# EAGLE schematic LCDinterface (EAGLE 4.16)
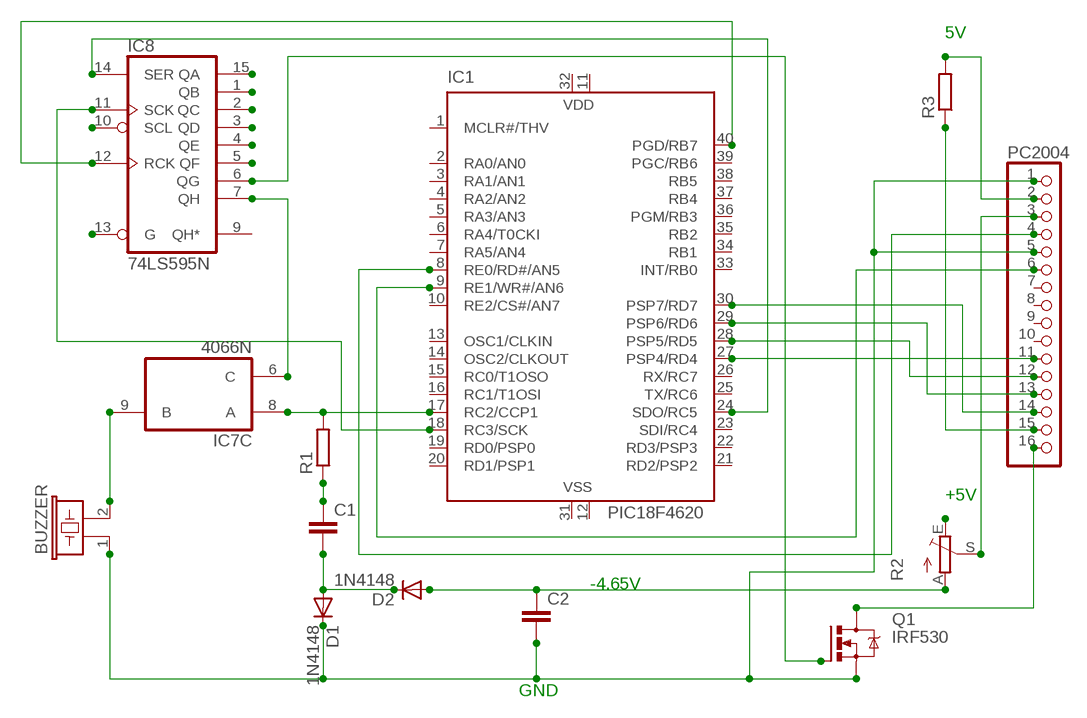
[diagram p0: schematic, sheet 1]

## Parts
BUZZER  B/C11L  [B/C11L]
C1  C-EU050-025X075  [C050-025X075]
C2  C-EU050-025X075  [C050-025X075]
D1  1N4148  [DO35-10]
D2  1N4148  [DO35-10]
IC1  PIC18F4620  PIC16F874P  [DIL40]
IC7  4066N  [DIL14]
IC8  74LS595N  [DIL16]
PC2004  PINHD-1X16  [1X16]
Q1  IRF530  [TO220BV]
R1  R-EU_0309/12  [0309/12]
R2  TRIM_EU-ECP10P  [ECP10P]
R3  R-EU_0309/12  [0309/12]

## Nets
N$1: IC7.6(C:C) IC8.7(QH)
N$2: IC1.17(RC2/CCP1) IC7.8(C:A) R1.2
N$3: BUZZER.2 IC7.9(C:B)
N$4: C1.1 R1.1
N$6: PC2004.15 R3.1
N$7: C1.2 D1.A D2.C
N$8: PC2004.2 R3.2
N$9: IC1.18(RC3/SCK) IC8.11(SCK)
N$10: PC2004.16 Q1.D
N$12: C2.1 D2.A R2.A
N$13: R2.E
N$14: IC8.6(QG) Q1.G
N$15: PC2004.3 R2.S
N$16: IC1.40(PGD/RB7) IC8.12(RCK)
N$19: IC1.24(SDO/RC5) IC8.14(SER)
N$20: IC1.30(PSP7/RD7) PC2004.14
N$21: IC1.29(PSP6/RD6) PC2004.13
N$22: IC1.28(PSP5/RD5) PC2004.12
N$23: IC1.27(PSP4/RD4) PC2004.11
N$28: IC1.8(RE0/RD#/AN5) PC2004.4
N$29: BUZZER.1 C2.2 D1.C PC2004.1 PC2004.5 Q1.S
N$30: IC1.9(RE1/WR#/AN6) PC2004.6
N$32: IC8.15(QA)
N$33: IC8.1(QB)
N$34: IC8.2(QC)
N$35: IC8.3(QD)
N$36: IC8.4(QE)
N$37: IC8.5(QF)
N$38: IC8.13(G)
N$39: IC8.10(SCL)
Unconnected: IC1.1(MCLR#/THV) IC1.2(RA0/AN0) IC1.3(RA1/AN1) IC1.4(RA2/AN2) IC1.5(RA3/AN3) IC1.6(RA4/T0CKI) IC1.7(RA5/AN4) IC1.10(RE2/CS#/AN7) IC1.13(OSC1/CLKIN) IC1.14(OSC2/CLKOUT) IC1.15(RC0/T1OSO) IC1.16(RC1/T1OSI) IC1.19(RD0/PSP0) IC1.20(RD1/PSP1) IC1.21(RD2/PSP2) IC1.22(RD3/PSP3) IC1.23(SDI/RC4) IC1.25(TX/RC6) IC1.26(RX/RC7) IC1.33(INT/RB0) IC1.34(RB1) IC1.35(RB2) IC1.36(PGM/RB3) IC1.37(RB4) IC1.38(RB5) IC1.39(PGC/RB6) IC7.1(A:A) IC7.2(A:B) IC7.3(B:B) IC7.4(B:A) IC7.5(B:C) IC7.10(D:B) IC7.11(D:A) IC7.12(D:C) IC7.13(A:C) IC8.9(QH*) PC2004.7 PC2004.8 PC2004.9 PC2004.10

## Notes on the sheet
- 5V
- +5V
- -4.65V
- GND

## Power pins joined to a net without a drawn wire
GND: IC8.8(GND)
VCC: IC8.16(VCC)
VDD: IC1.11(VDD) IC1.32(VDD) IC7.14(P:VDD)
VSS: IC1.12(VSS) IC1.31(VSS) IC7.7(P:VSS)

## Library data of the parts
BUZZER = buzzer:B/C11L: BUZZER
C1 C2 = rcl:C-EU: CAPACITOR, European symbol
D1 D2 = diode:1N4148: DIODE
IC1 = microchip:PIC16F87*: MICROCONTROLLER
IC7 = 40xx:4066: Quad bilateral ANALOG SWITCH
IC8 = 74xx-us:74*595: 8-bit SHIFT REGISTER, output latch
PC2004 = pinhead:PINHD-1X16: PIN HEADER
Q1 = transistor-power:IRF530: HEXFET Power MOSFET
R1 R3 = rcl:R-EU_: RESISTOR, European symbol
R2 = pot:TRIM_EU-: POTENTIOMETER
